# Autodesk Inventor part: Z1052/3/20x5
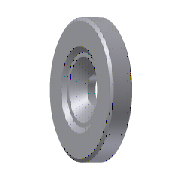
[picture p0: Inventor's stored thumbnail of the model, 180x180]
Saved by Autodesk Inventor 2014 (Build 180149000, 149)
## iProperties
Created: 2009-11
Part Number: Z1052/3/20x5
Material: DIN 1.1213
Description: Spacer
Document SubType Name: Modeling
Designer: gaom
Standard Revision: 1
Manufacturer: HASCO
Language: en-US
Size Designation: 3/20x5
Categories: <MemberInstance><Categories><Category DisplayName="Mold" InternalName="349578f2-f4d4-4954-8c09-8e99297a61c0" Mnemonic="MOLD"><Category DisplayName="Accessories"
Density: 7.81 g/cm^3
Appearance: Default
Author: gaom
IsCustomPart: 0
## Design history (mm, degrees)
sketch "Sketch1"
  geometry: L1 (0, -1)-(0, 6) reference; L2 (2.15, 0)-(2.15, 1.8); L3 (2.15, 1.8)-(4.55, 4.2); L4 (4.55, 4.2)-(5.2, 4.2); L5 (5.2, 4.2)-(6, 5); L6 (6, 5)-(10, 5); L7 (10, 5)-(10, 0); L8 (10, 0)-(2.15, 0); 1 further point
  constraints: 14 end point, 4 parallel, 2 perpendicular, 1 horizontal alignment
  dimensions: "d0" = 4.3 diameter of L2 L1 (= DI); "d2" = 45 deg angle of L8 L3 (= A_); "d3" = 0.8 distance between parallel lines of L6 L4 (= DD08); "d4" = 12 diameter of L5.end L1 (= AUSD); "d5" = 20 diameter of L7 L1 (= d); "d6" = 5 distance between parallel lines of L8 L6 (= h_); "d20" = 2.4 horizontal distance of L2.end L3.end (= D20)
revolve "Revolution1" sketch "Sketch1" stored, may be unused: angle "d7" = 90 deg
chamfer "Chamfer1" distance "d13" = 0.5; stored, may be unused: second distance "d14" = 2, angle "d15" = 45 deg
body "Solid1"
other parameters: "d" = 20 [user parameter; used in 1 equation term], "h_" = 5 [user parameter; used in 1 equation term], "DI" = 4.3 [user parameter; used in 1 equation term], "AUSD" = 12 [user parameter; used in 1 equation term], "d16" = 0, "d17" = 0, "d18" = 0, "D20" = 2.4 [user parameter; used in 1 equation term], "DD08" = 0.8 [user parameter; used in 1 equation term], "A_" = 45 deg [user parameter; used in 1 equation term]
